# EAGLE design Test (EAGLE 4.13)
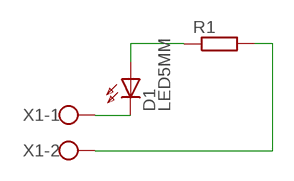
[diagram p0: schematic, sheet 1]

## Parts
D1  LED5MM  [LED5MM]
R1  R-EU_0309/12  [0309/12]
X1  W237-02P  [W237-132]

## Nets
N$1: D1.K(C) X1.1
N$2: D1.A R1.1
N$3: R1.2 X1.2

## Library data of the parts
D1 = led:LED5MM: LED
R1 = rcl:R-EU_: RESISTOR, European symbol
X1 = con-wago-508:W237-02P: WAGO SREW CLAMP

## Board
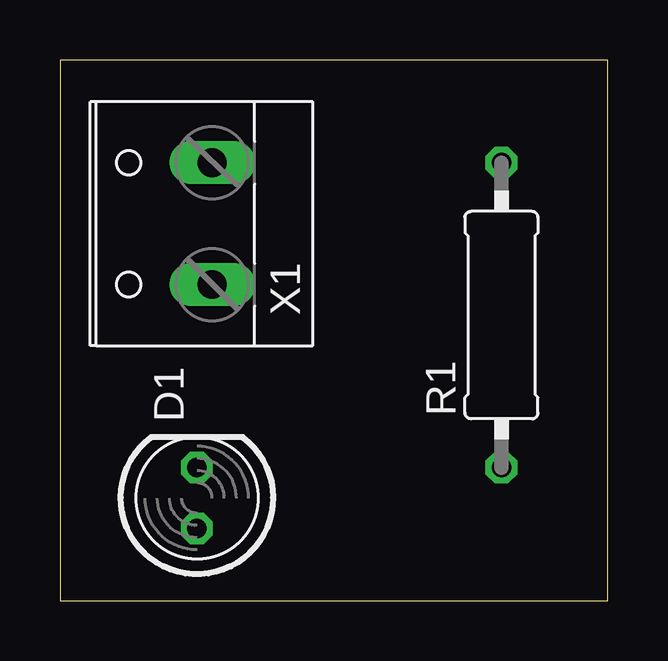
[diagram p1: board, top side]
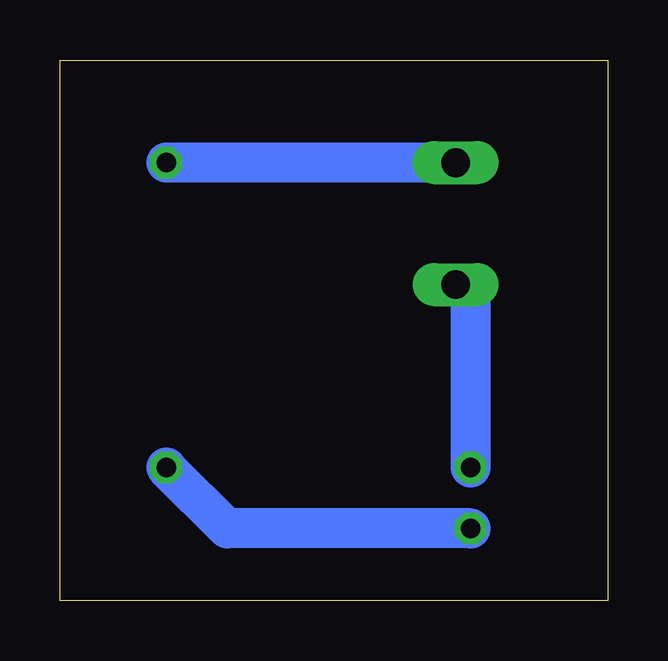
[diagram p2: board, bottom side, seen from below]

Size 22.84 x 22.53 mm. Coordinates in mm from the lower left corner, seen from the top.
Outline: 0,0 22.84,0 22.84,22.53 0,22.53 0,0
Copper layers 16: Bottom 0.035mm
Design rules "default": minimum track width 10mil, minimum drill 24mil, track to track 8mil, track to pad 8mil, pad to pad 8mil, via to via 8mil, smd to smd 8mil, copper to edge 40mil, drill to drill 8mil, minimum pad ring 10mil, minimum via ring 8mil, stop-mask expansion 0mil, vias tented up to drill 0mil, thermal gap 10mil

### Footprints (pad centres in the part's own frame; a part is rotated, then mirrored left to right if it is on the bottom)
LED5MM = drill 0.813 octagon: A -1.27,0; K 1.27,0
0309/12 = drill 0.813 octagon: 1 -6.35,0; 2 6.35,0
W237-132 = drill 1.194 long: 1 -2.54,-0.635; 2 2.54,-0.635

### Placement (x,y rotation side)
D1  5.71,4.28 90 top
R1  18.41,11.9 90 top
X1  5.71,15.71 90 top

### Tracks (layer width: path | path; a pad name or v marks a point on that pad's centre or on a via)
N$1
  Bottom 0.254: 5.71,13.17 X1.1
  Bottom 1.676: D1.K 5.71,13.17
N$2
  Bottom 1.676: D1.A 15.87,3.01 R1.1
N$3
  Bottom 1.676: X1.2 R1.2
